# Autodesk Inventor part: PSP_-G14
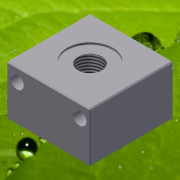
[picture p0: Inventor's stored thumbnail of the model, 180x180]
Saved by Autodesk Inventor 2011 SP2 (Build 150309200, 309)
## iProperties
Created: 2013-12
Part Number: PSP_-G14
Material: Алюминий - 6061
Document SubType Name: Modeling
Designer: dorohin
Mass: 88.3005 g
Surface Area: 100.58 cm^2
Volume: 32.5832 cm^3
Density: 2.71 g/cm^3
Author: dorohin
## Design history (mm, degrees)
sketch "Эскиз1"
  geometry: L1 (0, 0)-(0, 40); L2 (0, 40)-(40, 40); L3 (40, 40)-(40, 0); L4 (40, 0)-(0, 0); 1 further point
  constraints: 8 end point, 3 perpendicular, 1 coincident, 1 vertical
  dimensions: "d0" = 40 distance of L1.start L1.end; "d1" = 40 distance of L1.end L2.end
extrude "Выдавливание1" new body sketch "Эскиз1" distance "d2" = 24; taper "d3" = 0 deg
sketch "Эскиз2"
  geometry: L1 (0, 40)-(40, 0); L2 (40, 40)-(0, 0); 1 further point
  constraints: 4 end point, 1 midpoint, 1 perpendicular
hole "Отверстие1" sketch "Эскиз2" at (20, 20) diameter "d4" = 22; stored, may be unused: countersink angle "d8" = 90 deg, drill point angle "d10" = 0 deg; dims "d5" = 6, "d6" = 4, "d7" = 2, "d9" = 1
sketch "Эскиз3"
  geometry: C1 r 11 at (0, 0) reference; 1 further point
hole "Отверстие2" sketch "Эскиз3" at (0, 0) diameter "d11" = 11.445; stored, may be unused: countersink angle "d15" = 90 deg, drill point angle "d17" = 118 deg; dims "d12" = 14, "d13" = 4, "d14" = 2, "d16" = 19
sketch "Эскиз4"
  geometry: C1 r 5.723 at (0, 0) reference; 1 further point
hole "Отверстие3" sketch "Эскиз4" at (0, 0) diameter "d18" = 3; stored, may be unused: countersink angle "d22" = 90 deg, drill point angle "d24" = 118 deg; dims "d19" = 14, "d20" = 4, "d21" = 2, "d23" = 24
sketch "Эскиз5"
  geometry: L1 (0, -24)-(40, -24) reference; L2 (40, 0)-(40, -24) reference; L3 (0, 0)-(0, -24) reference; 2 further points
  dimensions: "d25" = 0 vertical distance of point (35, -18) point (5, -18); "d26" = 30 distance of point (5, -18) point (35, -18); "d27" = 6 distance from line of L1 point (5, -18); "d28" = 5 distance from line of point (5, -18) L3 (= d29); "d29" = 5 distance from line of L2 point (35, -18) (derived)
hole "Отверстие4" sketch "Эскиз5" at (5, -18), (35, -18) diameter "d30" = 6.5; stored, may be unused: countersink angle "d34" = 90 deg, drill point angle "d36" = 118 deg; dims "d31" = 14, "d32" = 4, "d33" = 2, "d35" = 45
sketch "Эскиз6"
  geometry: L1 (-4.5, 4.5)-(-35.5, 4.5); L2 (-35.5, 4.5)-(-35.5, 35.5); L3 (-35.5, 35.5)-(-4.5, 35.5); L4 (-4.5, 35.5)-(-4.5, 4.5); C1 r 1.5 at (-20, 20) reference; 5 further points
  constraints: 8 end point, 5 coincident, 1 vertical, 9 other
  dimensions: "d37" = 31 distance between parallel lines of L2 L4
hole "Отверстие5" sketch "Эскиз6" at (-4.5, 4.5), (-35.5, 4.5), (-35.5, 35.5), (-4.5, 35.5) diameter "d38" = 4.134; stored, may be unused: countersink angle "d42" = 90 deg, drill point angle "d44" = 118 deg; dims "d39" = 10, "d40" = 4, "d41" = 2, "d43" = 12
sketch "Эскиз7"
  geometry: L1 (4.558, 8.59)-(4.558, 35.61); L2 (4.558, 35.61)-(10.807, 35.61); L3 (10.807, 35.61)-(10.807, 8.59); L4 (10.807, 8.59)-(4.558, 8.59)
  constraints: 2 other
feature "Рельеф1" sketch "Эскиз7" dims "d24" = 118 deg, "d45" = 1, "d46" = 0
chamfer "Фаска1" distance "d47" = 0.5; stored, may be unused: second distance "d48" = 2, angle "d49" = 45 deg
node "Твердое тело1"
